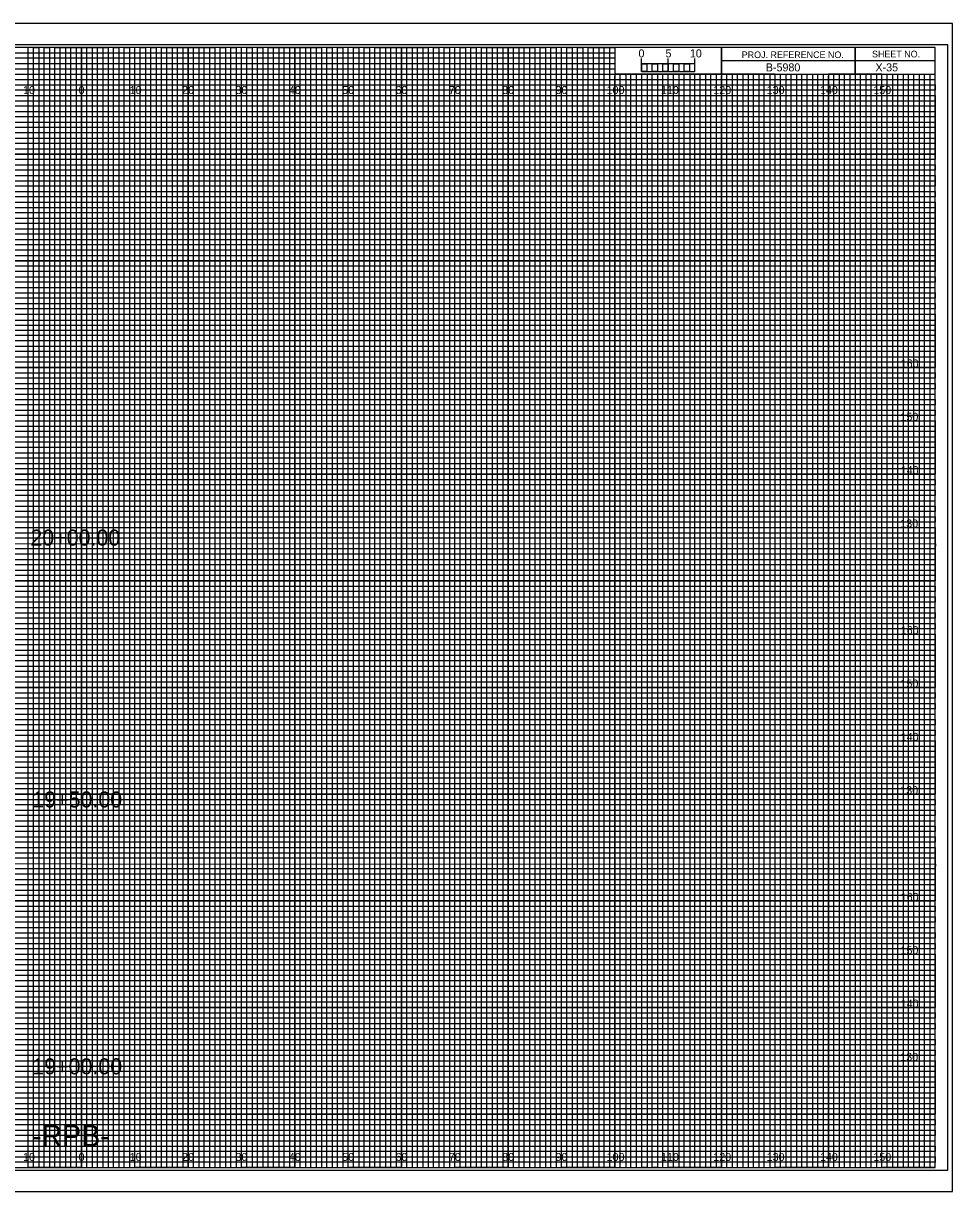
# Model space of a CAD drawing. Extents: x -13 to 323, y -5 to 1094.
# Drawn here: x 149.1 to 323.3, y 435.5 to 654.5 of the extents above; entities that cross this region are included whole.
import ezdxf

# ---------------------------------------------------------------- set-up
doc = ezdxf.new("R2010")
doc.units = 0
for name, color, linetype in [('Exist Cross Section Cell', 7, 'Continuous'), ('Exist XS Center Line Elevation Label', 7, 'Continuous'), ('Exist XS Ground Line', 7, 'Continuous'), ('Prop CMT Concrete Structures', 7, 'Continuous'), ('Prop CMT Guardrail Graphics', 7, 'Continuous'), ('Prop CMT Pvmt Course 1', 7, 'Continuous'), ('Prop CMT Pvmt Course 1 CG', 7, 'Continuous'), ('Prop CMT Pvmt Course 2', 7, 'Continuous'), ('Prop CMT Pvmt Course 3', 7, 'Continuous'), ('Prop CMT Pvmt Surface', 7, 'Continuous'), ('Prop CMT Pvmt Surface Shoulder', 7, 'Continuous'), ('Prop CMT Shld Paved Course 1', 7, 'Continuous'), ('Prop CMT Shld Paved Course 2', 7, 'Continuous'), ('Prop CMT Shld Paved Course 3', 7, 'Continuous'), ('Prop CMT Slope Grass', 7, 'Continuous'), ('Prop CMT Subgrade Earthwork', 7, 'Continuous'), ('Scratch_Level_1', 7, 'Continuous')]:
    doc.layers.add(name, color=color, linetype=linetype)

msp = doc.modelspace()

# ---------------------------------------------------------------- linework, layer by layer
at = {"layer": 'Exist XS Center Line Elevation Label'}
for points in [[(145, 440), (155, 440), (155, 650), (165, 650), (165, 440), (175, 440), (175, 650), (185, 650), (185, 440), (195, 440), (195, 650), (205, 650), (205, 440), (215, 440), (215, 650), (225, 650), (225, 440), (235, 440), (235, 650), (245, 650), (245, 440), (255, 440), (255, 650), (259.93, 650), (260, 650), (260, 645), (264.99, 645), (264.99, 440), (275, 440), (275, 645), (285, 645), (285, 440), (295, 440), (295, 645), (305, 645), (305, 440), (315, 440), (315, 645)], [(0, 645), (275, 645)], [(0, 625), (320, 625), (320, 635), (0, 635)], [(0, 605), (320, 605), (320, 615), (0, 615)], [(0, 585), (320, 585), (320, 595), (0, 595)], [(0, 565), (320, 565), (320, 575), (0, 575)], [(0, 545), (320, 545), (320, 555), (0, 555)], [(0, 525), (320, 525), (320, 535), (0, 535)], [(0, 505), (320, 505), (320, 515), (0, 515)], [(0, 485), (320, 485), (320, 495), (0, 495)], [(0, 465), (320, 465), (320, 475), (0, 475)], [(0, 445), (320, 445), (320, 455), (0, 455)]]:
    msp.add_lwpolyline(points, dxfattribs=at)
at = {"layer": 'Exist XS Ground Line'}
for p, q in [((150, 650), (140, 650)), ((150, 440), (150, 650)), ((170, 650), (160, 650)), ((160, 650), (160, 440)), ((170, 440), (170, 650)), ((190, 650), (180, 650)), ((180, 650), (180, 440)), ((190, 440), (190, 650)), ((210, 650), (200, 650)), ((200, 650), (200, 440)), ((210, 440), (210, 650)), ((230, 650), (220, 650)), ((220, 650), (220, 440)), ((230, 440), (230, 650)), ((250, 650), (240, 650)), ((240, 650), (240, 440)), ((250, 440), (250, 650)), ((260, 650), (260, 440)), ((270, 440), (270, 645)), ((290, 645), (280, 645)), ((280, 645), (280, 440)), ((290, 440), (290, 645)), ((310, 645), (300, 645)), ((300, 645), (300, 440)), ((310, 440), (310, 645)), ((160, 440), (150, 440)), ((180, 440), (170, 440)), ((200, 440), (190, 440)), ((220, 440), (210, 440)), ((240, 440), (230, 440)), ((260, 440), (250, 440)), ((280, 440), (270, 440)), ((300, 440), (290, 440)), ((320, 440), (310, 440)), ((320, 440), (320, 440))]:
    msp.add_line(p, q, dxfattribs=at)
for points in [[(0, 640), (320, 640), (320, 630), (0, 630)], [(0, 620), (320, 620), (320, 610), (0, 610)], [(0, 600), (320, 600), (320, 590), (0, 590)], [(0, 580), (320, 580), (320, 570), (0, 570)], [(0, 560), (320, 560), (320, 550), (0, 550)], [(0, 540), (320, 540), (320, 530), (0, 530)], [(0, 520), (320, 520), (320, 510), (0, 510)], [(0, 500), (320, 500), (320, 490), (0, 490)], [(0, 480), (320, 480), (320, 470), (0, 470)], [(0, 460), (320, 460), (320, 450), (0, 450)]]:
    msp.add_lwpolyline(points, dxfattribs=at)
at = {"layer": 'Prop CMT Pvmt Course 2'}
for p, q in [((265, 645.49), (265, 647.9)), ((265, 646.9), (265, 647.9)), ((270, 645.49), (270, 647.9)), ((275, 645.49), (275, 647.9)), ((275, 646.9), (275, 647.9))]:
    msp.add_line(p, q, dxfattribs=at)
for points in [[(275, 646.9), (265, 646.9), (265, 645.49), (275, 645.49)], [(265, 646.9), (266, 646.9), (266, 645.49), (265, 645.49)], [(267, 646.9), (268, 646.9), (268, 645.49), (267, 645.49)], [(269, 646.9), (270, 646.9), (270, 645.49), (269, 645.49)], [(271, 646.9), (272, 646.9), (272, 645.49), (271, 645.49)], [(273, 646.9), (274, 646.9), (274, 645.49), (273, 645.49)]]:
    msp.add_lwpolyline(points, close=True, dxfattribs=at)
at = {"layer": 'Prop CMT Pvmt Course 3'}
msp.add_lwpolyline([(-13.4, 435.5), (323.3, 435.5), (323.3, 654.5), (-13.4, 654.5)], close=True, dxfattribs=at)
at = {"layer": 'Prop CMT Pvmt Surface'}
for p, q in [((150, 440), (150, 650)), ((160, 440), (160, 650)), ((170, 440), (170, 650)), ((180, 440), (180, 650)), ((190, 440), (190, 650)), ((200, 440), (200, 650)), ((210, 440), (210, 650)), ((220, 440), (220, 650)), ((230, 440), (230, 650)), ((240, 440), (240, 650)), ((250, 440), (250, 650)), ((260, 440), (260, 644.69)), ((270, 440), (270, 644.69)), ((280, 440), (280, 644.69)), ((290, 440), (290, 644.69)), ((300, 440), (300, 644.69)), ((310, 440), (310, 644.69)), ((0, 640), (320, 640)), ((0, 630), (320, 630)), ((0, 620), (320, 620)), ((0, 610), (320, 610)), ((0, 600), (320, 600)), ((0, 590), (320, 590)), ((0, 580), (320, 580)), ((0, 570), (320, 570)), ((0, 560), (320, 560)), ((0, 550), (320, 550)), ((0, 540), (320, 540)), ((0, 530), (320, 530)), ((0, 520), (320, 520)), ((0, 510), (320, 510)), ((0, 500), (320, 500)), ((0, 490), (320, 490)), ((0, 480), (320, 480)), ((0, 470), (320, 470)), ((0, 460), (320, 460)), ((0, 450), (320, 450))]:
    msp.add_line(p, q, dxfattribs=at)
at = {"layer": 'Prop CMT Pvmt Surface Shoulder'}
for p, q in [((323.3, 654.5), (-13.4, 654.5)), ((-13.4, 435.5), (323.3, 435.5))]:
    msp.add_line(p, q, dxfattribs=at)
at = {"layer": 'Prop CMT Shld Paved Course 1'}
for p, q in [((0, 649), (260, 649)), ((260, 649), (260, 647.98)), ((260, 647.98), (0, 647.98)), ((0, 647), (260, 647)), ((260, 647), (260, 645.89)), ((260, 645.89), (0, 645.89)), ((0, 644), (320, 644))]:
    msp.add_line(p, q, dxfattribs=at)
for points in [[(0, 643), (270, 643), (320, 643), (320, 642), (0, 642)], [(0, 641), (320, 641), (320, 639), (0, 639)], [(0, 638), (320, 638), (320, 637), (0, 636.98)], [(0, 636), (320, 636), (320, 634), (0, 634)], [(0, 633), (320, 633), (320, 632), (0, 632)], [(0, 631), (320, 631), (320, 629), (0, 629)], [(0, 628), (320, 628), (320, 627), (0, 627)], [(0, 626), (320, 626), (320, 624), (0, 624)], [(0, 623), (320, 623), (320, 622), (0, 622)], [(0, 621), (320, 621), (320, 619), (0, 619)], [(0, 618), (320, 618), (320, 617), (0, 617)], [(0, 616), (320, 616), (320, 613.95), (320, 613), (320, 612), (0, 612)], [(0, 614), (320, 614), (320, 613), (0, 613)], [(0, 611), (320, 611), (320, 609), (0, 609.03)], [(0, 609.03), (320, 609), (320, 608), (0, 608)], [(0, 607), (320, 607), (320, 606), (0, 606)], [(0, 604), (320, 604), (320, 603), (0, 603)], [(0, 602), (320, 602), (320, 601), (0, 601)], [(-0.07, 598.89), (320, 598.89), (320, 597.88), (-0.07, 597.88)], [(0, 597), (320, 597), (320, 596), (0, 596)], [(0, 594), (320, 594), (320, 593), (0, 593)], [(0, 592), (320, 592), (320, 591), (0, 591)], [(0, 589), (320, 589), (320, 588), (0, 588)], [(0, 587), (320, 587), (320, 586), (0, 586)], [(0, 584), (320, 584), (320, 583), (0, 583)], [(0, 582), (320, 582), (320, 581), (0, 581)], [(0, 579), (320, 579), (319.99, 577.98), (0, 578)], [(0, 577), (320, 577), (320, 576), (0, 576)], [(0, 574), (320, 574), (320, 573), (0, 573)], [(0, 572), (320, 572), (320, 571), (0, 571)], [(0, 569), (320, 569), (320, 568), (0, 568)], [(0, 567), (320, 567), (320, 566), (0, 566)], [(0, 564), (320, 564), (320, 563), (0, 563)], [(0, 562), (320, 562), (320, 561), (0, 561)], [(0, 559), (320, 559), (320, 558), (0, 558)], [(0, 556.99), (320.07, 556.91), (320, 556), (0, 556)], [(0, 554), (320, 554), (320, 553), (0, 553)], [(0, 552), (320, 552), (320, 551), (0, 551)], [(0, 549), (320, 549), (320, 548), (0, 548)], [(0, 547), (320, 547), (320, 546), (0, 546)], [(0, 544), (320, 544), (320, 543), (0, 543)], [(0, 542), (320, 542), (320, 541), (0, 541)], [(0, 539), (320, 539), (320, 538), (0, 538)], [(0, 537), (320, 537), (320, 536), (0, 536)], [(0, 534), (320, 534), (320, 533), (0, 533)], [(0, 532), (320, 532), (320, 531), (0, 531)], [(0, 529), (320, 529), (320, 528), (0, 528)], [(0, 527), (320, 527), (320, 526), (0, 526)], [(0, 524), (320, 524), (320, 523), (0, 523)], [(0, 522), (320, 522), (320, 521), (0, 521)], [(0, 519), (320, 519), (319.99, 517.98), (0, 518)], [(0, 517), (320, 517), (320, 516), (0, 516)], [(0, 514), (320, 514), (320, 513), (0, 513)], [(0, 512), (320, 512), (320, 511), (0, 511)], [(0, 509), (320, 509), (320, 508), (0, 508)], [(0, 507), (320, 507), (320, 506), (0, 506)], [(0, 504), (320, 504), (320, 503), (0, 503)], [(0, 502), (320, 502), (320, 501), (0, 501)], [(0, 499), (320, 499), (320, 498), (0, 498)], [(0, 496.99), (320.07, 496.91), (320, 496), (0, 496)], [(0, 494), (320, 494), (320, 493), (0, 493)], [(0, 492), (320, 492), (320, 491), (0, 491)], [(0, 489), (320, 489), (320, 488), (0, 488)], [(0, 487), (320, 487), (320, 486), (0, 486)], [(0, 484), (320, 484), (320, 483), (0, 483)], [(0, 482), (320, 482), (320, 481), (0, 481)], [(0, 479), (320, 479), (320, 478), (0, 478)], [(0, 477), (320, 477), (320, 476), (0, 476)], [(0, 474), (320, 474), (320, 473), (0, 473)], [(0, 472), (320, 472), (320, 471), (0, 471)], [(0, 469), (320, 469), (320, 468), (0, 468)], [(0, 467), (320, 467), (320, 466), (0, 466)], [(0, 464), (320, 464), (320, 463), (0, 463)], [(0, 462), (320, 462), (320, 461), (0, 461)], [(0, 459), (320, 459), (320, 458), (0, 458)], [(0, 457), (320, 457), (320, 456), (0, 456)], [(0, 454), (320, 454), (320, 453), (0, 453)], [(0, 452), (320, 452), (320, 451), (0, 451)], [(0, 449), (320, 449), (320, 448), (0, 448)], [(0, 447), (320, 447), (320, 446), (0, 446)], [(0, 444), (320, 444), (320, 443), (0, 443)], [(0, 442), (320, 442), (320, 441), (0, 441)]]:
    msp.add_lwpolyline(points, dxfattribs=at)
at = {"layer": 'Prop CMT Shld Paved Course 2'}
for p, q in [((305, 650), (305, 645)), ((305, 645), (305, 650)), ((280, 647.5), (280, 645)), ((320, 647.49), (280, 647.49)), ((280, 645), (320, 645))]:
    msp.add_line(p, q, dxfattribs=at)
for points in [[(320, 650), (0, 650), (0, 440), (320, 440)], [(280, 650), (260, 650), (260, 645.03), (280, 645.03)], [(320, 650), (280, 650), (280, 645), (320, 645)]]:
    msp.add_lwpolyline(points, close=True, dxfattribs=at)
at = {"layer": 'Prop CMT Shld Paved Course 3'}
for p, q in [((267, 645), (266.01, 645)), ((266.01, 645), (266.01, 440)), ((267, 440), (267, 645)), ((269, 645), (268, 645)), ((268, 645), (268, 440)), ((269, 440), (269, 645)), ((266.01, 440), (265, 440)), ((268, 440), (267, 440))]:
    msp.add_line(p, q, dxfattribs=at)
for points in [[(150, 440), (151, 440), (151, 650), (152, 650), (152, 440)], [(152, 440), (153, 440), (153, 650), (154, 650), (154, 440)], [(155, 440), (156, 440), (156, 650), (157, 650), (157, 440)], [(157, 440), (158, 440), (158, 650), (159, 650), (159, 440)], [(160, 440), (161, 440), (161, 650), (162, 650), (162, 440)], [(162, 440), (163, 440), (163, 650), (164, 650), (164, 440)], [(165, 440), (166, 440), (166, 650), (167, 650), (167, 440)], [(167, 440), (168, 440), (168, 650), (169, 650), (169, 440)], [(170, 440), (171, 440), (171, 650), (172, 650), (172, 440)], [(172, 440), (173, 440), (173, 650), (174, 650), (174, 440)], [(175, 440), (176, 440), (176, 650), (177, 650), (177, 440)], [(177, 440), (178, 440), (178, 650), (179, 650), (179, 440)], [(180, 440), (181, 440), (181, 650), (182, 650), (182, 440)], [(182, 440), (183, 440), (183, 650), (184, 650), (184, 440)], [(185, 440), (186, 440), (186, 650), (187, 650), (187, 440)], [(187, 440), (188, 440), (188, 650), (189, 650), (189, 440)], [(190, 440), (191, 440), (191, 650), (192, 650), (192, 440)], [(192, 440), (193, 440), (193, 650), (194, 650), (194, 440)], [(195, 440), (196, 440), (196, 650), (197, 650), (197, 440)], [(197, 440), (198, 440), (198, 650), (199, 650), (199, 440)], [(200, 440), (201, 440), (201, 650), (202, 650), (202, 440)], [(202, 440), (203, 440), (203, 650), (204, 650), (204, 440)], [(205, 440), (206, 440), (206, 650), (207, 650), (207, 440)], [(207, 440), (208, 440), (208, 650), (209, 650), (209, 440)], [(210, 440), (211, 440), (211, 650), (212, 650), (212, 440)], [(212, 440), (213, 440), (213, 650), (214, 650), (214, 440)], [(215, 440), (216, 440), (216, 650), (217, 650), (217, 440)], [(217, 440), (218, 440), (218, 650), (219, 650), (219, 440)], [(220, 440), (221, 440), (221, 650), (222, 650), (222, 440)], [(222, 440), (223, 440), (223, 650), (224, 650), (224, 440)], [(225, 440), (226, 440), (226, 650), (227, 650), (227, 440)], [(227, 440), (228, 440), (228, 650), (229, 650), (229, 440)], [(230, 440), (231, 440), (231, 650), (232, 650), (232, 440)], [(232, 440), (233, 440), (233, 650), (234, 650), (234, 440)], [(235, 440), (236, 440), (236, 650), (237, 650), (237, 440)], [(237, 440), (238, 440), (238, 650), (239, 650), (239, 440)], [(240, 440), (241, 440), (241, 650), (242, 650), (242, 440)], [(242, 440), (243, 440), (243, 650), (244, 650), (244, 440)], [(245, 440), (246, 440), (246, 650), (247, 650), (247, 440)], [(247, 440), (248, 440), (248, 650), (249, 650), (249, 440)], [(250, 440), (251, 440), (251, 650), (252, 650), (252, 440)], [(252, 440), (253, 440), (253, 650), (254, 650), (254, 440)], [(255, 440), (256, 440), (256, 650), (257, 650), (257, 440)], [(257, 440), (258, 440), (258, 650), (259, 650), (259, 440)], [(260, 440), (261, 440), (261, 645), (262.02, 645), (262.02, 440)], [(262, 440), (263, 440), (263, 645), (263.99, 645), (263.99, 440)], [(270, 440), (270.98, 440), (270.98, 645), (272, 645), (272, 440)], [(272, 440), (273, 440), (273, 645), (274.05, 645), (274.05, 440)], [(275, 440), (276, 440), (276, 645), (277, 645), (277, 440)], [(277, 440), (278, 440), (278, 645), (279, 645), (279, 440)], [(280, 440), (281, 440), (281, 645), (282, 645), (282, 440)], [(282, 440), (283, 440), (283, 645), (284, 645), (284, 440)], [(285, 440), (286, 440), (286, 645), (287, 645), (287, 440)], [(287, 440), (288, 440), (288, 645), (289, 645), (289, 440)], [(290, 440), (291, 440), (291, 645), (292, 645), (292, 440)], [(292, 440), (293, 440), (293, 645), (294, 645), (294, 440)], [(295, 440), (296, 440), (296, 645), (297, 645), (297, 440)], [(297, 440), (298, 440), (298, 645), (299, 645), (299, 440)], [(300, 440), (301, 440), (301, 645), (302, 645), (302, 440)], [(302, 440), (303, 440), (303, 645), (304, 645), (304, 440)], [(305, 440), (306, 440), (306, 645), (307, 645), (307, 440)], [(307, 440), (308, 440), (308, 645), (309, 645), (309, 440)], [(310, 440), (311, 440), (311, 645), (312, 645), (312, 440)], [(312, 440), (313, 440), (313, 645), (314, 645), (314, 440)], [(315, 440), (316, 440), (316, 645), (317, 645), (317, 440)], [(317, 440), (318, 440), (318, 645), (319, 645), (319, 440)]]:
    msp.add_lwpolyline(points, dxfattribs=at)
at = {"layer": 'Prop CMT Subgrade Earthwork'}
msp.add_lwpolyline([(-10.8, 439.5), (322.4, 439.5), (322.4, 650.5), (-10.8, 650.5)], close=True, dxfattribs=at)

# ---------------------------------------------------------------- texts
at = {"layer": 'Exist Cross Section Cell'}
for s, p in [('10', (149.04, 641.25)), ('0', (159.45, 641.25)), ('0', (159.45, 641.25)), ('10', (169.04, 641.25)), ('20', (178.86, 641.25)), ('30', (188.86, 641.25)), ('40', (198.86, 641.25)), ('50', (208.86, 641.25)), ('60', (218.86, 641.25)), ('70', (228.86, 641.25)), ('80', (238.86, 641.25)), ('90', (248.86, 641.25)), ('100', (258.44, 641.25)), ('110', (268.62, 641.25)), ('120', (278.44, 641.25)), ('130', (288.44, 641.25)), ('140', (298.44, 641.25)), ('150', (308.44, 641.25)), ('10', (149.04, 441.25)), ('0', (159.45, 441.25)), ('0', (159.45, 441.25)), ('10', (169.04, 441.25)), ('20', (178.86, 441.25)), ('30', (188.86, 441.25)), ('40', (198.86, 441.25)), ('50', (208.86, 441.25)), ('60', (218.86, 441.25)), ('70', (228.86, 441.25)), ('80', (238.86, 441.25)), ('90', (248.86, 441.25)), ('100', (258.44, 441.25)), ('110', (268.62, 441.25)), ('120', (278.44, 441.25)), ('130', (288.44, 441.25)), ('140', (298.44, 441.25)), ('150', (308.44, 441.25))]:
    msp.add_text(s, height=1.5, dxfattribs=at).set_placement(p)
at = {"layer": 'Prop CMT Concrete Structures'}
msp.add_text('-RPB-', height=4, dxfattribs=at).set_placement((150.72, 444))
at = {"layer": 'Prop CMT Guardrail Graphics'}
msp.add_text('X-35', height=1.5, dxfattribs=at).set_placement((308.83, 645.5))
at = {"layer": 'Prop CMT Pvmt Course 1'}
for s, p in [('160', (313.57, 590)), ('150', (313.52, 580)), ('140', (313.57, 570)), ('130', (313.49, 560)), ('160', (313.57, 540)), ('150', (313.52, 530)), ('140', (313.57, 520)), ('130', (313.49, 510)), ('160', (313.57, 490)), ('150', (313.52, 480)), ('140', (313.57, 470)), ('130', (313.49, 460))]:
    msp.add_text(s, height=1.5, dxfattribs=at).set_placement(p)
at = {"layer": 'Prop CMT Pvmt Course 1 CG'}
for s, p in [('5', (269.47, 648.12)), ('10', (274.04, 648.12))]:
    msp.add_text(s, height=1.5, dxfattribs=at).set_placement(p)
at = {"layer": 'Prop CMT Pvmt Course 2'}
msp.add_text('0', height=1.5, dxfattribs=at).set_placement((264.41, 648.12))
at = {"layer": 'Prop CMT Shld Paved Course 2'}
for s, p in [('PROJ. REFERENCE NO.', (283.77, 647.99)), ('SHEET NO.', (308.19, 648.12))]:
    msp.add_text(s, height=1.25, dxfattribs=at).set_placement(p)
at = {"layer": 'Prop CMT Slope Grass'}
for s, p in [('20+00.00', (150.41, 556.6)), ('19+50.00', (150.77, 507.52)), ('19+00.00', (150.77, 457.49))]:
    msp.add_text(s, height=3, dxfattribs=at).set_placement(p)
at = {"layer": 'Scratch_Level_1'}
msp.add_text('B-5980', height=1.5, dxfattribs=at).set_placement((288.28, 645.5))

doc.saveas('drawing.dxf')
